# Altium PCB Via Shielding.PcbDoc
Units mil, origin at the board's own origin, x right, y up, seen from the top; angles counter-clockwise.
Board outline 3150 x 1890 mil, 2 copper layers (Top Layer, Bottom Layer); 3 components, 54 nets, 62 pads, 114 vias.
Unrouted connection lines stored in the file: 11.
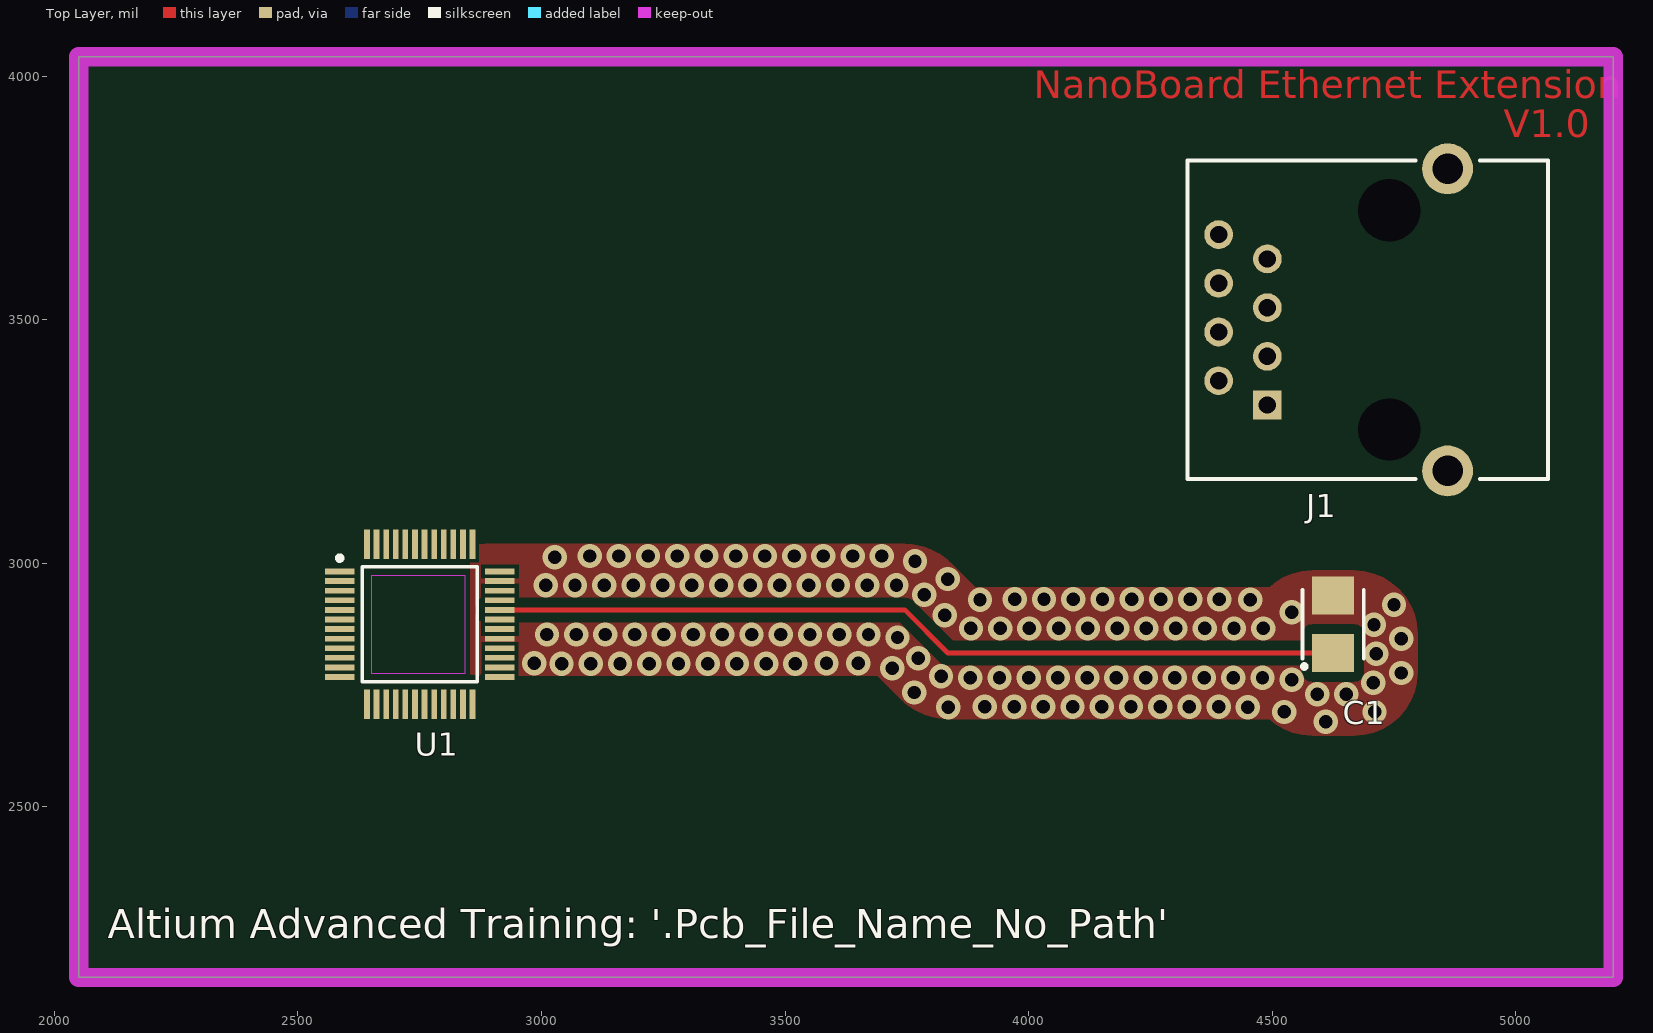
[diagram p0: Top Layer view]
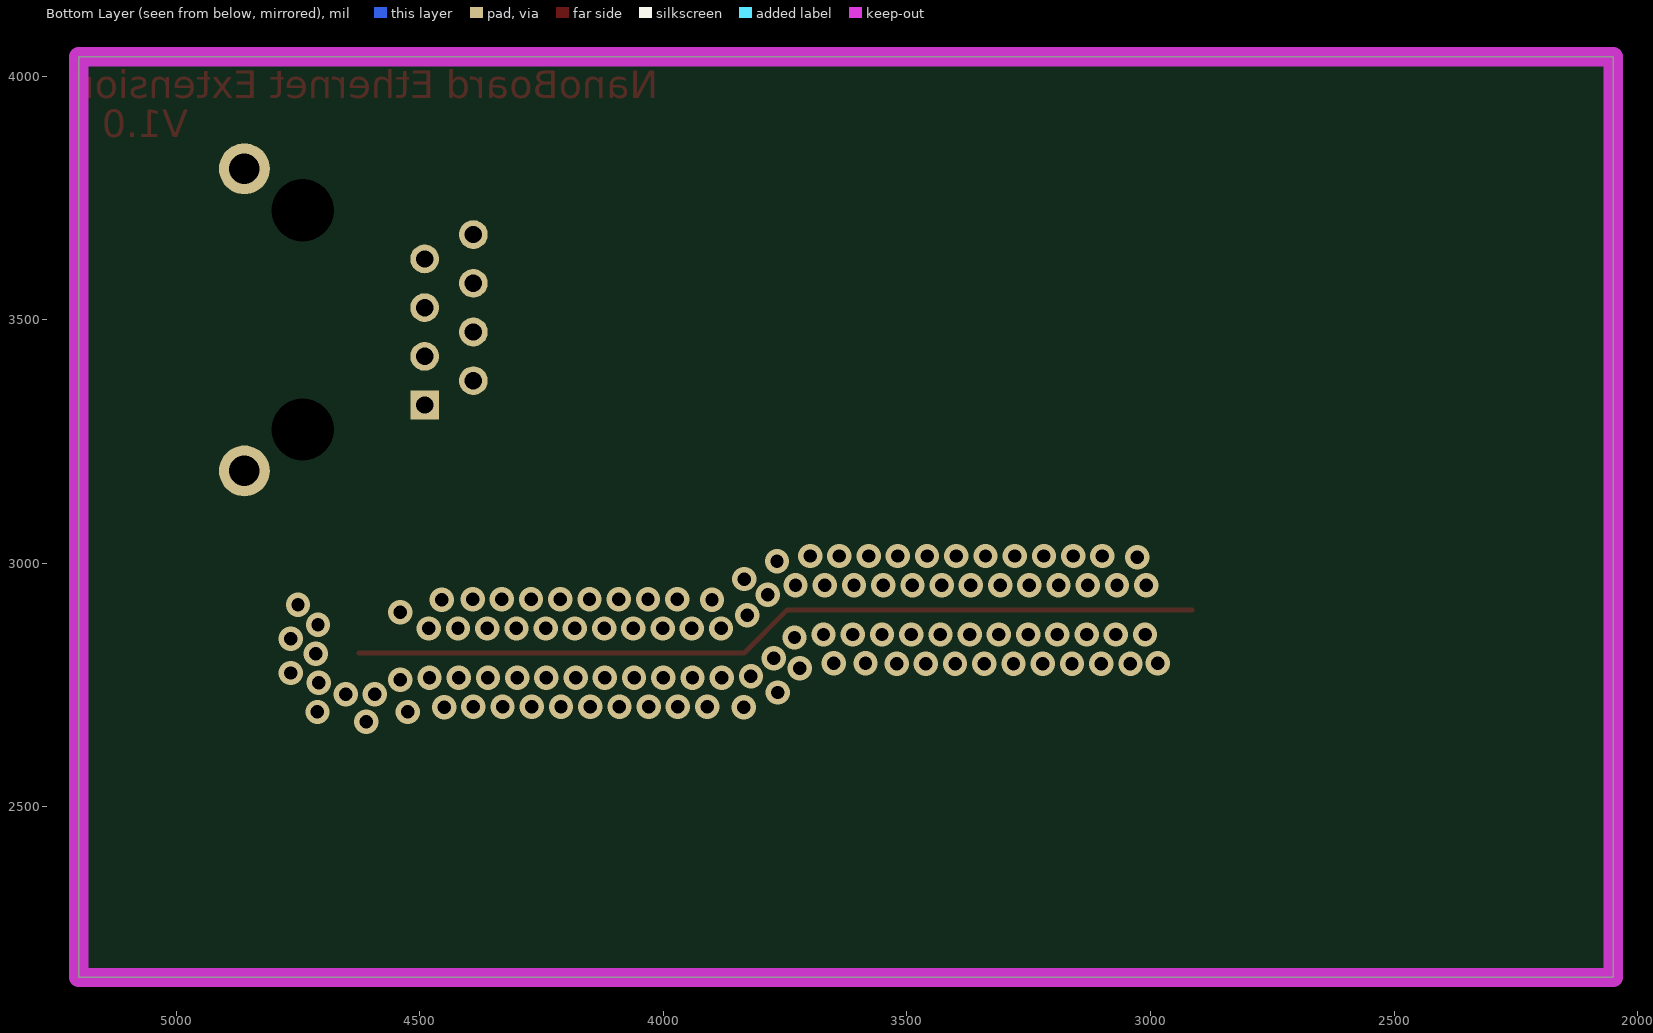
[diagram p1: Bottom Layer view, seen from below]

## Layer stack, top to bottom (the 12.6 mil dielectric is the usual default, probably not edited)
Top Solder: solder mask 0.4, Solder Resist, Dk 3.5
Top Layer: signal copper 1.4
Dielectric1: dielectric 12.6, FR-4, Dk 4.8
Bottom Layer: signal copper 1.4
Bottom Solder: solder mask 0.4, Solder Resist, Dk 3.5

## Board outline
2050,2150 2050,4040 5200,4040 5200,2150

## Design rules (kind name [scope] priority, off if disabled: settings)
Clearance Clearance_1 [(HasFootprint('TSQFP50P900X900-48'))] p1: gap=7.87 ignorepadtopadclearanceinfootprint=FALSE except(0: Arc-Hole Track-Hole SMDPad-Hole THPad-Hole Via-Hole Fill-Hole Poly-Hole Region-Hole Text-Hole)
Clearance [All] p2: gap=9.45 ignorepadtopadclearanceinfootprint=FALSE except(0: Arc-Hole Track-Hole SMDPad-Hole THPad-Hole Via-Hole Fill-Hole Poly-Hole Region-Hole Text-Hole)
FabricationTestPointUsage TestPointUsage [All] p1 off: valid=0 allowmultiple=FALSE
FabricationTestpoint Testpoint [All] p1 off: side=3 testpointundercomponent=TRUE minsize=40 maxsize=100 preferedsize=60 minholesize=0 maxholesize=40 preferedholesize=32 testpointgrid=1 allowsidetop=TRUE allowsidebottom=TRUE usegrid=TRUE gridtolerance=0.01
HoleSize [All] p1: absolutevalues=TRUE maxlimit=137.79 minlimit=1 maxpercent=80.000 minpercent=20.000
PolygonConnect [All] p1: connectstyle=Direct reliefconductorwidth=10 reliefentries=4 polygonreliefangle="90 Angle" airgapwidth=10
RoutingVias [All] p1: holewidth=27.56 width=50 viastyle="Through Hole" minholewidth=27.56 minwidth=50 maxholewidth=27.56 maxwidth=50
SilkToSolderMaskClearance SilkscreenOverComponentPads [IsPad] p1: minsilkscreentomaskgap=10 clearancetoexposedcopper=TRUE
SolderMaskExpansion [All] p1: expansion=4 istentingtop=FALSE
Width Width_1 [(InNet('3V3') OR InNet('GND') OR InNet('PWFBIN') OR InNet('PWFBOUT'))] p1: maxlimit=20 minlimit=5 preferedwidth=10
Width [All] p2: maxlimit=10 minlimit=10 preferedwidth=10
26 further rules are at their usual default settings.

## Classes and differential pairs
component class PHY: R7

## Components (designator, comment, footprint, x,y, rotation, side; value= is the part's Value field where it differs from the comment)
C1 "22uF 10V" CAPC3528 4625,2875 r90 top
J1 "RJ45 HEADER" 95122-2881 4625,3500 r90 top
U1 "RTL8201CL" TSQFP50P900X900-48 2750,2875 r0 top

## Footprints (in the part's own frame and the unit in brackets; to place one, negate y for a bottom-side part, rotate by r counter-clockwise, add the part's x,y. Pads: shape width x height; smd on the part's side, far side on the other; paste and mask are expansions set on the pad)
95122-2881 [mm]
  rect 1.5x1.5 hole 0.9: 1(-4.445,3.43)
  round 1.5 hole 0.9: 2(-3.175,5.97) 3(-1.905,3.43) 4(-0.635,5.97) 5(0.635,3.43) 6(1.905,5.97) 7(3.175,3.43) 8(4.445,5.97)
  round 2.65 hole 1.6: MH1(-7.875,-5.97) MH2(7.875,-5.97)
  round 2.95 hole 3.25 unplated: MH3(-5.715,-2.92) MH4(5.715,-2.92)
  silkscreen extent -8.3,-11.2 8.3,7.6
CAPC3528 [mm]
  rect 2x2.2 smd: 1(-1.5,0) 2(1.5,0)
  silkscreen extent -2.3,-1.6 1.8,1.6
TSQFP50P900X900-48 [mm]
  rect 1.55x0.3 smd: 1(-4.175,2.75) 2(-4.175,2.25) 3(-4.175,1.75) 4(-4.175,1.25) 5(-4.175,0.75) 6(-4.175,0.25) 7(-4.175,-0.25) 8(-4.175,-0.75) 9(-4.175,-1.25) 10(-4.175,-1.75) 11(-4.175,-2.25) 12(-4.175,-2.75) 25(4.175,-2.75) 26(4.175,-2.25) 27(4.175,-1.75) 28(4.175,-1.25) 29(4.175,-0.75) 30(4.175,-0.25) 31(4.175,0.25) 32(4.175,0.75) 33(4.175,1.25) 34(4.175,1.75) 35(4.175,2.25) 36(4.175,2.75)
  rect 0.3x1.55 smd: 13(-2.75,-4.175) 14(-2.25,-4.175) 15(-1.75,-4.175) 16(-1.25,-4.175) 17(-0.75,-4.175) 18(-0.25,-4.175) 19(0.25,-4.175) 20(0.75,-4.175) 21(1.25,-4.175) 22(1.75,-4.175) 23(2.25,-4.175) 24(2.75,-4.175) 37(2.75,4.175) 38(2.25,4.175) 39(1.75,4.175) 40(1.25,4.175) 41(0.75,4.175) 42(0.25,4.175) 43(-0.25,4.175) 44(-0.75,4.175) 45(-1.25,4.175) 46(-1.75,4.175) 47(-2.25,4.175) 48(-2.75,4.175)
  silkscreen extent -4.3,-3 3,3.57

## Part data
C1: library part "Cap Pol1", "Polarized Capacitor (Radial)"
J1: library part 95122-2881, "Right Angle, Standard Profile, External Shield PCB Jack"
U1: "Realtek Ethernet PHY tranceiver"

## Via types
v1: diameter 50, hole 27.56, Top Layer to Bottom Layer, 114 vias

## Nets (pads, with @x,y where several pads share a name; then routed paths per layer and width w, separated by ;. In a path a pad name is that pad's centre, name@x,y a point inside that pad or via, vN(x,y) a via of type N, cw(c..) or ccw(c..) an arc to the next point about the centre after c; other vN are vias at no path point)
3V3: U1.14 U1.37 U1.38 U1.39 U1.41 U1.44 U1.48
3V3A: U1.36
COL: U1.1
CRS: U1.23
GND: C1.2 U1.11 U1.17 U1.29 U1.35 U1.40 U1.43 U1.45
  other v1: 4610,2675 4525,2695 4710,2695 3835,2705 3910.05,2705.33 3970.05,2705.33 4030.05,2705.33 4090.05,2705.33 4150.05,2705.33 4210.05,2705.33 4270.05,2705.33 4330.05,2705.33 4390.05,2705.33 4450,2705 4592.24,2731.5 4652.24,2731.5 3765,2735 4707.59,2754.65 4539.87,2760.78 3880.05,2765.46 3940.05,2765.46 4000.05,2765.46 4060.05,2765.46 4120.05,2765.46 4180.05,2765.46 4240.05,2765.46 4300.05,2765.46 4360.05,2765.46 4420.05,2765.46 4480.05,2765.46 3820.1,2767.95 4765,2775 3720,2785 3041.12,2793.91 3101.12,2793.91 3161.12,2793.91 3221.12,2793.91 3281.12,2793.91 3341.12,2793.91 3401.12,2793.91 3461.12,2793.91 3521.12,2793.91 2985,2795 3585,2795 3650,2795 3773.22,2805.39 4713.38,2814.37 4765,2845 3730.79,2847.81 3011.12,2854.04 3071.12,2854.04 3131.12,2854.04 3191.12,2854.04 3251.12,2854.04 3311.12,2854.04 3371.12,2854.04 3431.12,2854.04 3491.12,2854.04 3551.12,2854.04 3611.12,2854.04 3671.12,2854.04 3881.49,2866.43 3941.49,2866.43 4001.49,2866.43 4061.49,2866.43 4121.49,2866.43 4181.49,2866.43 4241.49,2866.43 4301.49,2866.43 4361.49,2866.43 4421.49,2866.43 4481.49,2866.43 4708.85,2874.2 3827.93,2893.46 4540,2900 4750,2915 3900,2925 4455,2925 3971.49,2926.56 4031.49,2926.56 4091.49,2926.56 4151.49,2926.56 4211.49,2926.56 4271.49,2926.56 4331.49,2926.56 4391.49,2926.56 3785.5,2935.89 3008.63,2955.01 3068.63,2955.01 3128.63,2955.01 3188.63,2955.01 3248.63,2955.01 3308.63,2955.01 3368.63,2955.01 3428.63,2955.01 3488.63,2955.01 3548.63,2955.01 3608.63,2955.01 3668.63,2955.01 3728.63,2955.01 3834.15,2967.84 3766.65,3004.02 3027.21,3012.89 3098.63,3015.14 3158.63,3015.14 3218.63,3015.14 3278.63,3015.14 3338.63,3015.14 3398.63,3015.14 3458.63,3015.14 3518.63,3015.14 3578.63,3015.14 3638.63,3015.14 3698.63,3015.14
LED0: U1.9
LED1: U1.10
LED2: U1.12
LED3: U1.13
LED4: U1.15
MDC: U1.25
MDIO: U1.26
NetC5_1: 
NetC6_2: 
NetC7_2: U1.46
NetC8_2: U1.47
NetC9_1: 
NetC9_2: 
NetC10_2: 
NetC11_2: 
NetDS1_2: 
NetDS2_1: 
NetDS3_1: 
NetDS4_1: 
NetDS5_1: 
NetJ1_1: 
NetJ1_2: 
NetJ1_3: 
NetJ1_4: 
NetJ1_6: 
NetJ1_7: 
NetR2_1: U1.31
NetR3_1: U1.30
NetR5_2: U1.33
NetR6_2: U1.34
NetR10_2: 
NetR11_2: 
NetR14_2: U1.28
PWFBIN: U1.8
PWFBOUT: C1.1 U1.32 | length 1747.3
  Top Layer w10: U1.32 3745.47,2904.53 3834.06,2815.94 C1.1
RESETB: U1.42
RXC: U1.16
RXD0: U1.21
RXD1: U1.20
RXD2: U1.19
RXD3: U1.18
RXDV: U1.22
RXER: U1.24
TXC: U1.7
TXD0: U1.6
TXD1: U1.5
TXD2: U1.4
TXD3: U1.3
TXEN: U1.2
pads on no net: J1.1 J1.2 J1.3 J1.4 J1.5 J1.6 J1.7 J1.8 J1.MH1 J1.MH2 J1.MH3 J1.MH4 U1.27

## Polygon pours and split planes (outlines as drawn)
GND on Top Layer "Top Layer-GND" (solid, pour order 0): 2951.15,3040.07 3745.47,3040.07 3750.57,3039.67 3755.68,3039.67 3760.73,3038.87 3765.83,3038.47 3770.8,3037.27 3775.85,3036.47 3780.71,3034.89 3785.68,3033.7 3789.51,3032.11 3790.41,3031.74 3795.27,3030.16 3799.1,3028.58 3803.65,3026.26 3808.38,3024.3 3812.74,3021.63 3817.29,3019.31 3820.04,3017.31 3821.43,3016.3 3825.79,3013.63 3829.67,3010.31 3833.81,3007.31 3833.81,3007.3 3837.43,3003.69 3841.31,3000.37 3890.2,2951.49 4494.54,2951.49 4505.21,2960.59 4522.62,2971.26 4541.48,2979.07 4561.34,2983.84 4581.69,2985.44 4668.31,2985.44 4688.66,2983.84 4708.52,2979.07 4727.38,2971.26 4744.79,2960.59 4760.32,2947.33 4773.58,2931.8 4784.25,2914.39 4792.07,2895.53 4796.83,2875.67 4798.44,2855.32 4798.44,2776.57 4796.83,2756.22 4792.07,2736.36 4784.25,2717.5 4773.58,2700.09 4760.32,2684.56 4744.79,2671.3 4727.38,2660.63 4708.52,2652.82 4688.66,2648.05 4668.31,2646.45 4581.69,2646.45 4561.34,2648.05 4541.48,2652.82 4522.62,2660.63 4505.21,2671.3 4494.54,2680.4 3834.06,2680.4 3828.96,2680.81 3823.85,2680.81 3823.84,2680.81 3818.8,2681.61 3813.7,2682.01 3808.73,2683.2 3803.68,2684 3798.81,2685.58 3793.84,2686.77 3790.02,2688.36 3789.12,2688.73 3784.26,2690.31 3780.43,2691.89 3780.43,2691.9 3775.87,2694.22 3771.15,2696.17 3766.79,2698.84 3762.24,2701.16 3762.24,2701.17 3762.23,2701.17 3758.1,2704.17 3753.74,2706.84 3749.85,2710.16 3745.72,2713.17 3742.1,2716.78 3738.21,2720.1 3689.33,2768.99 2951.15,2768.99 2944.88,2768.49 2883.86,2768.49 2863.5,2770.1 2843.65,2774.86 2824.78,2782.68 2807.37,2793.35 2791.84,2806.61 2778.58,2822.13 2767.91,2839.54 2760.1,2858.41 2755.33,2878.27 2753.73,2898.62 2753.73,2910.43 2755.33,2930.79 2760.1,2950.64 2767.91,2969.51 2778.58,2986.92 2791.84,3002.45 2807.37,3015.71 2824.78,3026.38 2843.65,3034.19 2863.5,3038.96 2883.86,3040.56 2944.88,3040.56

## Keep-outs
Top Layer:
  rectangle: 2650,2774.86 2843.65,2975
Keep-Out Layer:
  the board outline again, w39.37

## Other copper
Top Layer:
  pour cut-out: 2947.36,2929.81 3745.47,2929.81 3748.5,2929.2 3753.07,2928.29 3753.08,2928.29 3756.9,2926.71 3760.77,2924.12 3763.35,2922.4 3844.53,2841.22 4561.83,2841.22 4561.83,2855.32 4563.34,2862.92 4567.65,2869.36 4574.09,2873.67 4581.69,2875.18 4668.31,2875.18 4675.91,2873.67 4682.35,2869.36 4686.66,2862.92 4688.17,2855.32 4688.17,2776.57 4686.66,2768.97 4682.35,2762.53 4675.91,2758.22 4668.31,2756.71 4581.69,2756.71 4574.09,2758.22 4567.65,2762.53 4563.34,2768.97 4561.83,2776.57 4561.83,2790.67 3834.06,2790.67 3834.05,2790.67 3826.49,2792.17 3826.45,2792.18 3822.63,2793.76 3818.75,2796.35 3816.18,2798.07 3735,2879.25 2947.36,2879.25 2944.88,2878.76 2883.86,2878.76 2876.26,2880.27 2869.81,2884.57 2865.5,2891.02 2863.99,2898.62 2863.99,2910.43 2865.5,2918.04 2869.81,2924.48 2876.26,2928.79 2883.86,2930.3 2944.88,2930.3
  text "NanoBoard Ethernet Extension" at 4010,3955 h57.09
  text "V1.0" at 4975,3875 h57.09

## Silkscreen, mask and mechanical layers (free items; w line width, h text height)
Top Overlay:
  text "Altium Advanced Training: '.Pcb_File_Name_No_Path'" at 2110,2229.99 h60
